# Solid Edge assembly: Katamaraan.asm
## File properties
Author: Henri
Template: Normal.asm
Last saved by: Henri
Revision: 5
Application: Solid Edge
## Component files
20 kiil.par
4 esiklaasid.par
ljeaknad paremal.par
5 tagumised aknad.par
9 mast.par
3 katus.par
17 radari alus.psm
18 radar.par
19 katuse juhtpaneel.par
7 lamamistool.par
1 katamaraan.par
8 wc.par
2 kate.par
10 juhtpaneel.par
11 uks.par
14 siseuks.par
12 vannituba.par
k.par
13 lounge.par
16 ventilatsiooniava.par
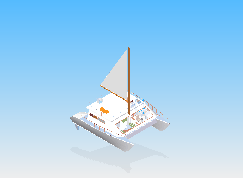
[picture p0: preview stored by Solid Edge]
